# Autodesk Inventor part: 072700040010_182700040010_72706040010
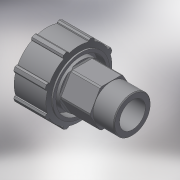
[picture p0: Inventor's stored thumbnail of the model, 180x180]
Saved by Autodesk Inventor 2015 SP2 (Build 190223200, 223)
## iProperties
Created: 2017-04
Part Number: 072700040010_182700040010_72706040010
Material: Generic
Description: PLASSON BRASS THREADED ADAPTOR 40-1"
Document SubType Name: Modeling
Designer: KIM
Density: 1 g/cm^3
Appearance: Default
Author: KIM
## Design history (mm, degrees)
derived "07270.ipt"
feature "Solid1::07270.ipt"
tag "TaggingFeature1"
body "Solid1"
other parameters: "d1" = 33.249, "d2" = 81, "d3" = 19, "d7" = 82, "d8" = 65.6, "d12" = 23.2743, "d13" = 26.5992, "d15" = 61.5, "d17" = 32.4, "d18" = 19, "d19" = 22.8, "d40" = 34, "d41" = 39.1, "d42" = 135 deg, "d43" = 100 deg, "d44" = 29.808, "d45" = 58.425, "d46" = 76.26, "d47" = 35 deg, "d48" = 17.5 deg, "d50" = 0, "d52" = 360 deg, "d54" = 1.64, "d57" = 1.64, "d61" = 0, "d62" = 0.66498, "d65" = 0.99747, "R_" = 33.249, "E_" = 82, "H_" = 81, "l_2" = 19, "Wrench" = 34
